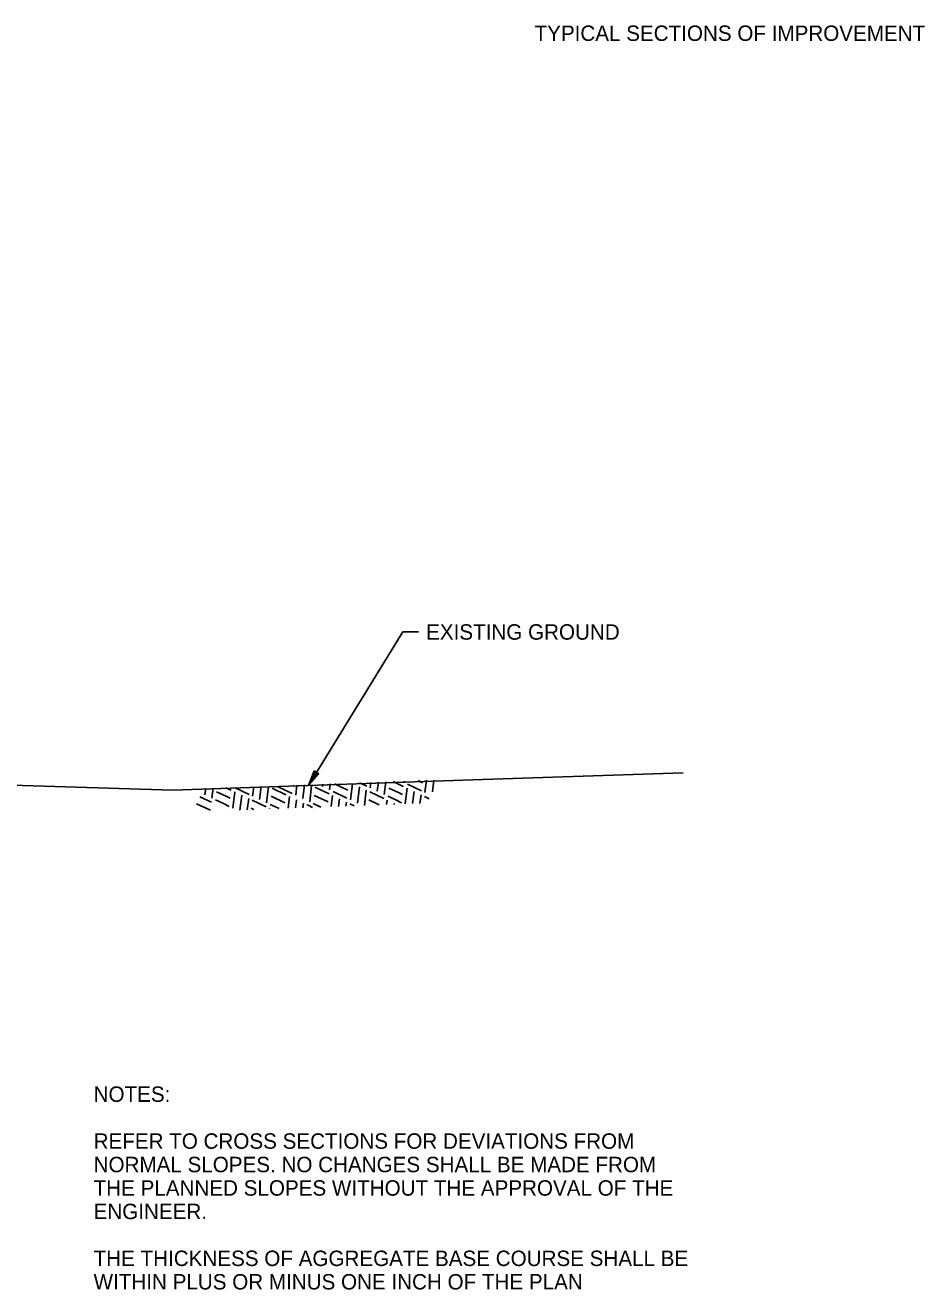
# Model space of a CAD drawing. Extents: x 1824008 to 1828864, y 689441 to 689870.
# Drawn here: x 1828827.02 to 1828862.02, y 689820.31 to 689869.51 of the extents above; entities that cross this region are included whole.
import ezdxf

# ---------------------------------------------------------------- set-up
doc = ezdxf.new("R2010")
doc.units = 0
for name, color, linetype in [('1', 7, 'Continuous'), ('19', 7, 'Continuous'), ('R_Draft', 7, 'Continuous')]:
    doc.layers.add(name, color=color, linetype=linetype)

msp = doc.modelspace()

# ---------------------------------------------------------------- linework, layer by layer
at = {"layer": '1'}
for p, q in [((1828835.868, 689839.516), (1828835.912, 689839.882)), ((1828835.868, 689839.516), (1828835.912, 689839.882)), ((1828835.868, 689839.516), (1828835.912, 689839.882)), ((1828836.139, 689839.387), (1828836.2, 689839.892)), ((1828836.139, 689839.387), (1828836.2, 689839.892)), ((1828836.139, 689839.387), (1828836.2, 689839.892)), ((1828836.41, 689839.259), (1828836.486, 689839.887)), ((1828836.41, 689839.259), (1828836.486, 689839.887)), ((1828836.41, 689839.259), (1828836.486, 689839.887)), ((1828837.409, 689839.616), (1828836.867, 689839.873)), ((1828837.409, 689839.616), (1828836.867, 689839.873)), ((1828837.409, 689839.616), (1828836.867, 689839.873)), ((1828837.447, 689839.93), (1828837.43, 689839.938)), ((1828837.447, 689839.93), (1828837.43, 689839.938)), ((1828837.447, 689839.93), (1828837.43, 689839.938)), ((1828837.544, 689839.552), (1828837.592, 689839.944)), ((1828837.544, 689839.552), (1828837.592, 689839.944)), ((1828837.544, 689839.552), (1828837.592, 689839.944)), ((1828837.815, 689839.423), (1828837.88, 689839.954)), ((1828837.815, 689839.423), (1828837.88, 689839.954)), ((1828837.815, 689839.423), (1828837.88, 689839.954)), ((1828838.087, 689839.295), (1828838.163, 689839.923)), ((1828838.087, 689839.295), (1828838.163, 689839.923)), ((1828838.087, 689839.295), (1828838.163, 689839.923)), ((1828838.343, 689839.837), (1828838.298, 689839.858)), ((1828838.343, 689839.837), (1828838.298, 689839.858)), ((1828838.343, 689839.837), (1828838.298, 689839.858)), ((1828838.588, 689839.887), (1828838.6, 689839.981)), ((1828838.588, 689839.887), (1828838.6, 689839.981)), ((1828838.588, 689839.887), (1828838.6, 689839.981)), ((1828838.859, 689839.758), (1828838.888, 689839.991)), ((1828838.859, 689839.758), (1828838.888, 689839.991)), ((1828838.859, 689839.758), (1828838.888, 689839.991)), ((1828839.575, 689839.751), (1828839.055, 689839.998)), ((1828839.575, 689839.751), (1828839.055, 689839.998)), ((1828839.575, 689839.751), (1828839.055, 689839.998)), ((1828839.673, 689839.373), (1828839.749, 689840.001)), ((1828839.673, 689839.373), (1828839.749, 689840.001)), ((1828839.944, 689839.245), (1828840.02, 689839.873)), ((1828839.944, 689839.245), (1828840.02, 689839.873)), ((1828839.944, 689839.245), (1828840.02, 689839.873)), ((1828840.31, 689839.901), (1828840.03, 689840.034)), ((1828840.31, 689839.901), (1828840.03, 689840.034)), ((1828840.31, 689839.901), (1828840.03, 689840.034)), ((1828840.446, 689839.837), (1828840.472, 689840.05)), ((1828840.446, 689839.837), (1828840.472, 689840.05)), ((1828840.446, 689839.837), (1828840.472, 689840.05)), ((1828840.717, 689839.708), (1828840.76, 689840.061)), ((1828840.717, 689839.708), (1828840.76, 689840.061)), ((1828840.717, 689839.708), (1828840.76, 689840.061)), ((1828840.988, 689839.58), (1828841.048, 689840.071)), ((1828840.988, 689839.58), (1828841.048, 689840.071)), ((1828840.988, 689839.58), (1828841.048, 689840.071)), ((1828841.697, 689839.908), (1828841.331, 689840.082)), ((1828841.697, 689839.908), (1828841.331, 689840.082)), ((1828841.697, 689839.908), (1828841.331, 689840.082)), ((1828841.742, 689839.887), (1828841.697, 689839.908)), ((1828841.742, 689839.887), (1828841.697, 689839.908)), ((1828841.742, 689839.887), (1828841.697, 689839.908)), ((1828841.761, 689840.044), (1828841.768, 689840.098)), ((1828841.761, 689840.044), (1828841.768, 689840.098)), ((1828841.761, 689840.044), (1828841.768, 689840.098)), ((1828842.439, 689839.723), (1828841.897, 689839.98)), ((1828842.439, 689839.723), (1828841.897, 689839.98)), ((1828842.439, 689839.723), (1828841.897, 689839.98)), ((1828842.477, 689840.037), (1828842.306, 689840.118)), ((1828842.477, 689840.037), (1828842.306, 689840.118)), ((1828842.477, 689840.037), (1828842.306, 689840.118)), ((1828842.574, 689839.659), (1828842.631, 689840.13)), ((1828842.574, 689839.659), (1828842.631, 689840.13)), ((1828842.574, 689839.659), (1828842.631, 689840.13)), ((1828842.863, 689839.676), (1828842.919, 689840.14)), ((1828842.863, 689839.676), (1828842.919, 689840.14)), ((1828842.863, 689839.676), (1828842.919, 689840.14)), ((1828834.262, 689839.28), (1828833.815, 689839.492)), ((1828834.262, 689839.28), (1828833.815, 689839.492)), ((1828834.262, 689839.28), (1828833.815, 689839.492)), ((1828834.01, 689839.566), (1828834.04, 689839.812)), ((1828834.01, 689839.566), (1828834.04, 689839.812)), ((1828834.01, 689839.566), (1828834.04, 689839.812)), ((1828834.281, 689839.437), (1828834.328, 689839.823)), ((1828834.281, 689839.437), (1828834.328, 689839.823)), ((1828834.281, 689839.437), (1828834.328, 689839.823)), ((1828834.733, 689839.223), (1828834.417, 689839.373)), ((1828834.733, 689839.223), (1828834.417, 689839.373)), ((1828834.733, 689839.223), (1828834.417, 689839.373)), ((1828834.862, 689839.494), (1828834.455, 689839.687)), ((1828834.862, 689839.494), (1828834.455, 689839.687)), ((1828834.862, 689839.494), (1828834.455, 689839.687)), ((1828834.99, 689839.766), (1828834.83, 689839.842)), ((1828834.99, 689839.766), (1828834.83, 689839.842)), ((1828834.99, 689839.766), (1828834.83, 689839.842)), ((1828834.997, 689839.43), (1828834.862, 689839.494)), ((1828834.997, 689839.43), (1828834.862, 689839.494)), ((1828834.997, 689839.43), (1828834.862, 689839.494)), ((1828835.035, 689839.744), (1828834.99, 689839.766)), ((1828835.035, 689839.744), (1828834.99, 689839.766)), ((1828835.035, 689839.744), (1828834.99, 689839.766)), ((1828835.095, 689839.052), (1828835.171, 689839.68)), ((1828835.095, 689839.052), (1828835.171, 689839.68)), ((1828835.095, 689839.052), (1828835.171, 689839.68)), ((1828835.732, 689839.58), (1828835.19, 689839.837)), ((1828835.732, 689839.58), (1828835.19, 689839.837)), ((1828835.732, 689839.58), (1828835.19, 689839.837)), ((1828835.372, 689838.974), (1828835.442, 689839.552)), ((1828835.372, 689838.974), (1828835.442, 689839.552)), ((1828835.372, 689838.974), (1828835.442, 689839.552)), ((1828835.66, 689838.984), (1828835.713, 689839.423)), ((1828835.66, 689838.984), (1828835.713, 689839.423)), ((1828835.66, 689838.984), (1828835.713, 689839.423)), ((1828836.391, 689839.102), (1828835.849, 689839.359)), ((1828836.391, 689839.102), (1828835.849, 689839.359)), ((1828836.391, 689839.102), (1828835.849, 689839.359)), ((1828837.126, 689839.252), (1828836.583, 689839.509)), ((1828837.126, 689839.252), (1828836.583, 689839.509)), ((1828837.126, 689839.252), (1828836.583, 689839.509)), ((1828837.164, 689839.566), (1828836.622, 689839.823)), ((1828837.164, 689839.566), (1828836.622, 689839.823)), ((1828837.164, 689839.566), (1828836.622, 689839.823)), ((1828837.244, 689839.043), (1828837.299, 689839.502)), ((1828837.244, 689839.043), (1828837.299, 689839.502)), ((1828837.244, 689839.043), (1828837.299, 689839.502)), ((1828837.532, 689839.053), (1828837.57, 689839.373)), ((1828837.532, 689839.053), (1828837.57, 689839.373)), ((1828837.532, 689839.053), (1828837.57, 689839.373)), ((1828838.802, 689839.288), (1828838.26, 689839.544)), ((1828838.802, 689839.288), (1828838.26, 689839.544)), ((1828838.802, 689839.288), (1828838.26, 689839.544)), ((1828838.84, 689839.601), (1828838.343, 689839.837)), ((1828838.84, 689839.601), (1828838.343, 689839.837)), ((1828838.84, 689839.601), (1828838.343, 689839.837)), ((1828838.924, 689839.105), (1828838.976, 689839.537)), ((1828838.924, 689839.105), (1828838.976, 689839.537)), ((1828838.924, 689839.105), (1828838.976, 689839.537)), ((1828839.537, 689839.437), (1828838.995, 689839.694)), ((1828839.537, 689839.437), (1828838.995, 689839.694)), ((1828839.537, 689839.437), (1828838.995, 689839.694)), ((1828839.212, 689839.115), (1828839.247, 689839.409)), ((1828839.212, 689839.115), (1828839.247, 689839.409)), ((1828839.212, 689839.115), (1828839.247, 689839.409)), ((1828840.22, 689839.153), (1828840.291, 689839.744)), ((1828840.22, 689839.153), (1828840.291, 689839.744)), ((1828840.22, 689839.153), (1828840.291, 689839.744)), ((1828840.794, 689839.174), (1828840.389, 689839.366)), ((1828840.794, 689839.174), (1828840.389, 689839.366)), ((1828840.794, 689839.174), (1828840.389, 689839.366)), ((1828840.969, 689839.423), (1828840.427, 689839.68)), ((1828840.969, 689839.423), (1828840.427, 689839.68)), ((1828840.969, 689839.423), (1828840.427, 689839.68)), ((1828841.083, 689839.185), (1828841.105, 689839.359)), ((1828841.083, 689839.185), (1828841.105, 689839.359)), ((1828841.083, 689839.185), (1828841.105, 689839.359)), ((1828841.44, 689839.366), (1828841.124, 689839.516)), ((1828841.44, 689839.366), (1828841.124, 689839.516)), ((1828841.44, 689839.366), (1828841.124, 689839.516)), ((1828841.568, 689839.637), (1828841.162, 689839.83)), ((1828841.568, 689839.637), (1828841.162, 689839.83)), ((1828841.568, 689839.637), (1828841.162, 689839.83)), ((1828841.666, 689839.259), (1828841.44, 689839.366)), ((1828841.666, 689839.259), (1828841.44, 689839.366)), ((1828841.666, 689839.259), (1828841.44, 689839.366)), ((1828841.704, 689839.573), (1828841.568, 689839.637)), ((1828841.704, 689839.573), (1828841.568, 689839.637)), ((1828841.704, 689839.573), (1828841.568, 689839.637)), ((1828841.803, 689839.211), (1828841.878, 689839.823)), ((1828841.803, 689839.211), (1828841.878, 689839.823)), ((1828841.803, 689839.211), (1828841.878, 689839.823)), ((1828842.091, 689839.222), (1828842.149, 689839.694)), ((1828842.091, 689839.222), (1828842.149, 689839.694)), ((1828842.091, 689839.222), (1828842.149, 689839.694)), ((1828842.379, 689839.232), (1828842.42, 689839.566)), ((1828842.379, 689839.232), (1828842.42, 689839.566)), ((1828842.379, 689839.232), (1828842.42, 689839.566)), ((1828842.739, 689839.414), (1828842.555, 689839.502)), ((1828842.739, 689839.414), (1828842.555, 689839.502)), ((1828842.739, 689839.414), (1828842.555, 689839.502)), ((1828834.224, 689838.967), (1828833.686, 689839.221)), ((1828834.224, 689838.967), (1828833.686, 689839.221)), ((1828834.224, 689838.967), (1828833.686, 689839.221)), ((1828834.959, 689839.116), (1828834.733, 689839.223)), ((1828834.959, 689839.116), (1828834.733, 689839.223)), ((1828834.959, 689839.116), (1828834.733, 689839.223)), ((1828834.94, 689838.958), (1828834.94, 689838.959)), ((1828834.94, 689838.958), (1828834.94, 689838.959)), ((1828834.94, 689838.958), (1828834.94, 689838.959)), ((1828835.918, 689838.994), (1828835.811, 689839.045)), ((1828835.918, 689838.994), (1828835.811, 689839.045)), ((1828835.918, 689838.994), (1828835.811, 689839.045)), ((1828836.524, 689839.016), (1828836.526, 689839.038)), ((1828836.524, 689839.016), (1828836.526, 689839.038)), ((1828836.524, 689839.016), (1828836.526, 689839.038)), ((1828836.894, 689839.03), (1828836.545, 689839.195)), ((1828836.894, 689839.03), (1828836.545, 689839.195)), ((1828836.894, 689839.03), (1828836.545, 689839.195)), ((1828837.82, 689839.064), (1828837.842, 689839.245)), ((1828837.82, 689839.064), (1828837.842, 689839.245)), ((1828837.82, 689839.064), (1828837.842, 689839.245)), ((1828838.022, 689839.159), (1828837.977, 689839.181)), ((1828838.022, 689839.159), (1828837.977, 689839.181)), ((1828838.022, 689839.159), (1828837.977, 689839.181)), ((1828838.194, 689839.078), (1828838.022, 689839.159)), ((1828838.194, 689839.078), (1828838.022, 689839.159)), ((1828838.194, 689839.078), (1828838.022, 689839.159)), ((1828838.519, 689839.09), (1828838.222, 689839.23)), ((1828838.519, 689839.09), (1828838.222, 689839.23)), ((1828838.519, 689839.09), (1828838.222, 689839.23)), ((1828839.5, 689839.126), (1828839.518, 689839.28)), ((1828839.5, 689839.126), (1828839.518, 689839.28)), ((1828839.5, 689839.126), (1828839.518, 689839.28)), ((1828839.819, 689839.138), (1828839.654, 689839.216)), ((1828839.819, 689839.138), (1828839.654, 689839.216)), ((1828839.819, 689839.138), (1828839.654, 689839.216)), ((1828841.371, 689839.195), (1828841.376, 689839.23)), ((1828841.371, 689839.195), (1828841.376, 689839.23)), ((1828841.371, 689839.195), (1828841.376, 689839.23))]:
    msp.add_line(p, q, dxfattribs=at)
msp.add_lwpolyline([(1828852.627, 689840.421), (1828844.044, 689840.132), (1828832.759, 689839.746), (1828826.49, 689839.939), (1828822.529, 689839.679)], dxfattribs=at)
at = {"layer": 'R_Draft'}
for p, q in [((1828838.042, 689839.926), (1828838.265, 689840.493)), ((1828838.443, 689840.383), (1828838.042, 689839.926)), ((1828838.116, 689840.067), (1828838.309, 689840.461)), ((1828838.402, 689840.405), (1828838.139, 689840.056)), ((1828838.265, 689840.493), (1828838.443, 689840.383)), ((1828835.868, 689839.516), (1828835.912, 689839.882)), ((1828836.139, 689839.387), (1828836.2, 689839.892)), ((1828836.41, 689839.259), (1828836.486, 689839.887)), ((1828837.409, 689839.616), (1828836.867, 689839.873)), ((1828837.447, 689839.93), (1828837.43, 689839.938)), ((1828837.544, 689839.552), (1828837.592, 689839.944)), ((1828837.815, 689839.423), (1828837.88, 689839.954)), ((1828838.087, 689839.295), (1828838.163, 689839.923)), ((1828838.343, 689839.837), (1828838.298, 689839.858)), ((1828838.588, 689839.887), (1828838.6, 689839.981)), ((1828838.859, 689839.758), (1828838.888, 689839.991)), ((1828839.575, 689839.751), (1828839.055, 689839.998)), ((1828839.673, 689839.373), (1828839.749, 689840.001)), ((1828839.944, 689839.245), (1828840.02, 689839.873)), ((1828840.31, 689839.901), (1828840.03, 689840.034)), ((1828840.446, 689839.837), (1828840.472, 689840.05)), ((1828840.717, 689839.708), (1828840.76, 689840.061)), ((1828840.988, 689839.58), (1828841.048, 689840.071)), ((1828841.697, 689839.908), (1828841.331, 689840.082)), ((1828841.742, 689839.887), (1828841.697, 689839.908)), ((1828841.761, 689840.044), (1828841.768, 689840.098)), ((1828842.439, 689839.723), (1828841.897, 689839.98)), ((1828842.477, 689840.037), (1828842.306, 689840.118)), ((1828842.574, 689839.659), (1828842.631, 689840.13)), ((1828842.863, 689839.676), (1828842.919, 689840.14)), ((1828834.262, 689839.28), (1828833.815, 689839.492)), ((1828834.01, 689839.566), (1828834.04, 689839.812)), ((1828834.281, 689839.437), (1828834.328, 689839.823)), ((1828834.733, 689839.223), (1828834.417, 689839.373)), ((1828834.862, 689839.494), (1828834.455, 689839.687)), ((1828834.99, 689839.766), (1828834.83, 689839.842)), ((1828834.997, 689839.43), (1828834.862, 689839.494)), ((1828835.035, 689839.744), (1828834.99, 689839.766)), ((1828835.095, 689839.052), (1828835.171, 689839.68)), ((1828835.732, 689839.58), (1828835.19, 689839.837)), ((1828835.372, 689838.974), (1828835.442, 689839.552)), ((1828835.66, 689838.984), (1828835.713, 689839.423)), ((1828836.391, 689839.102), (1828835.849, 689839.359)), ((1828837.126, 689839.252), (1828836.583, 689839.509)), ((1828837.164, 689839.566), (1828836.622, 689839.823)), ((1828837.244, 689839.043), (1828837.299, 689839.502)), ((1828837.532, 689839.053), (1828837.57, 689839.373)), ((1828838.802, 689839.288), (1828838.26, 689839.544)), ((1828838.84, 689839.601), (1828838.343, 689839.837)), ((1828838.924, 689839.105), (1828838.976, 689839.537)), ((1828839.537, 689839.437), (1828838.995, 689839.694)), ((1828839.212, 689839.115), (1828839.247, 689839.409)), ((1828840.22, 689839.153), (1828840.291, 689839.744)), ((1828840.794, 689839.174), (1828840.389, 689839.366)), ((1828840.969, 689839.423), (1828840.427, 689839.68)), ((1828841.083, 689839.185), (1828841.105, 689839.359)), ((1828841.44, 689839.366), (1828841.124, 689839.516)), ((1828841.568, 689839.637), (1828841.162, 689839.83)), ((1828841.666, 689839.259), (1828841.44, 689839.366)), ((1828841.704, 689839.573), (1828841.568, 689839.637)), ((1828841.803, 689839.211), (1828841.878, 689839.823)), ((1828842.091, 689839.222), (1828842.149, 689839.694)), ((1828842.379, 689839.232), (1828842.42, 689839.566)), ((1828842.739, 689839.414), (1828842.555, 689839.502)), ((1828834.224, 689838.967), (1828833.686, 689839.221)), ((1828834.959, 689839.116), (1828834.733, 689839.223)), ((1828834.94, 689838.958), (1828834.94, 689838.959)), ((1828835.918, 689838.994), (1828835.811, 689839.045)), ((1828836.524, 689839.016), (1828836.526, 689839.038)), ((1828836.894, 689839.03), (1828836.545, 689839.195)), ((1828837.82, 689839.064), (1828837.842, 689839.245)), ((1828838.022, 689839.159), (1828837.977, 689839.181)), ((1828838.194, 689839.078), (1828838.022, 689839.159)), ((1828838.519, 689839.09), (1828838.222, 689839.23)), ((1828839.5, 689839.126), (1828839.518, 689839.28)), ((1828839.819, 689839.138), (1828839.654, 689839.216)), ((1828841.371, 689839.195), (1828841.376, 689839.23))]:
    msp.add_line(p, q, dxfattribs=at)
msp.add_lwpolyline([(1828842.318, 689845.902), (1828841.718, 689845.902), (1828838.042, 689839.926)], dxfattribs=at)

# ---------------------------------------------------------------- texts
at = {"layer": '1'}
msp.add_text('TYPICAL SECTIONS OF IMPROVEMENT', height=0.6, dxfattribs=at).set_placement((1828846.838, 689868.898))
at = {"layer": '19'}
for s, p in [('NOTES:', (1828829.679, 689827.619)), ('REFER TO CROSS SECTIONS FOR DEVIATIONS FROM', (1828829.679, 689825.794)), ('NORMAL SLOPES. NO CHANGES SHALL BE MADE FROM ', (1828829.679, 689824.881)), ('THE PLANNED SLOPES WITHOUT THE APPROVAL OF THE', (1828829.679, 689823.969)), ('ENGINEER.', (1828829.679, 689823.056)), ('THE THICKNESS OF AGGREGATE BASE COURSE SHALL BE', (1828829.679, 689821.231)), ('WITHIN PLUS OR MINUS ONE INCH OF THE PLAN ', (1828829.679, 689820.319))]:
    msp.add_text(s, height=0.6, dxfattribs=at).set_placement(p)
at = {"layer": 'R_Draft'}
msp.add_text('EXISTING GROUND', height=0.6, dxfattribs=at).set_placement((1828842.618, 689845.602))

doc.saveas('drawing.dxf')
